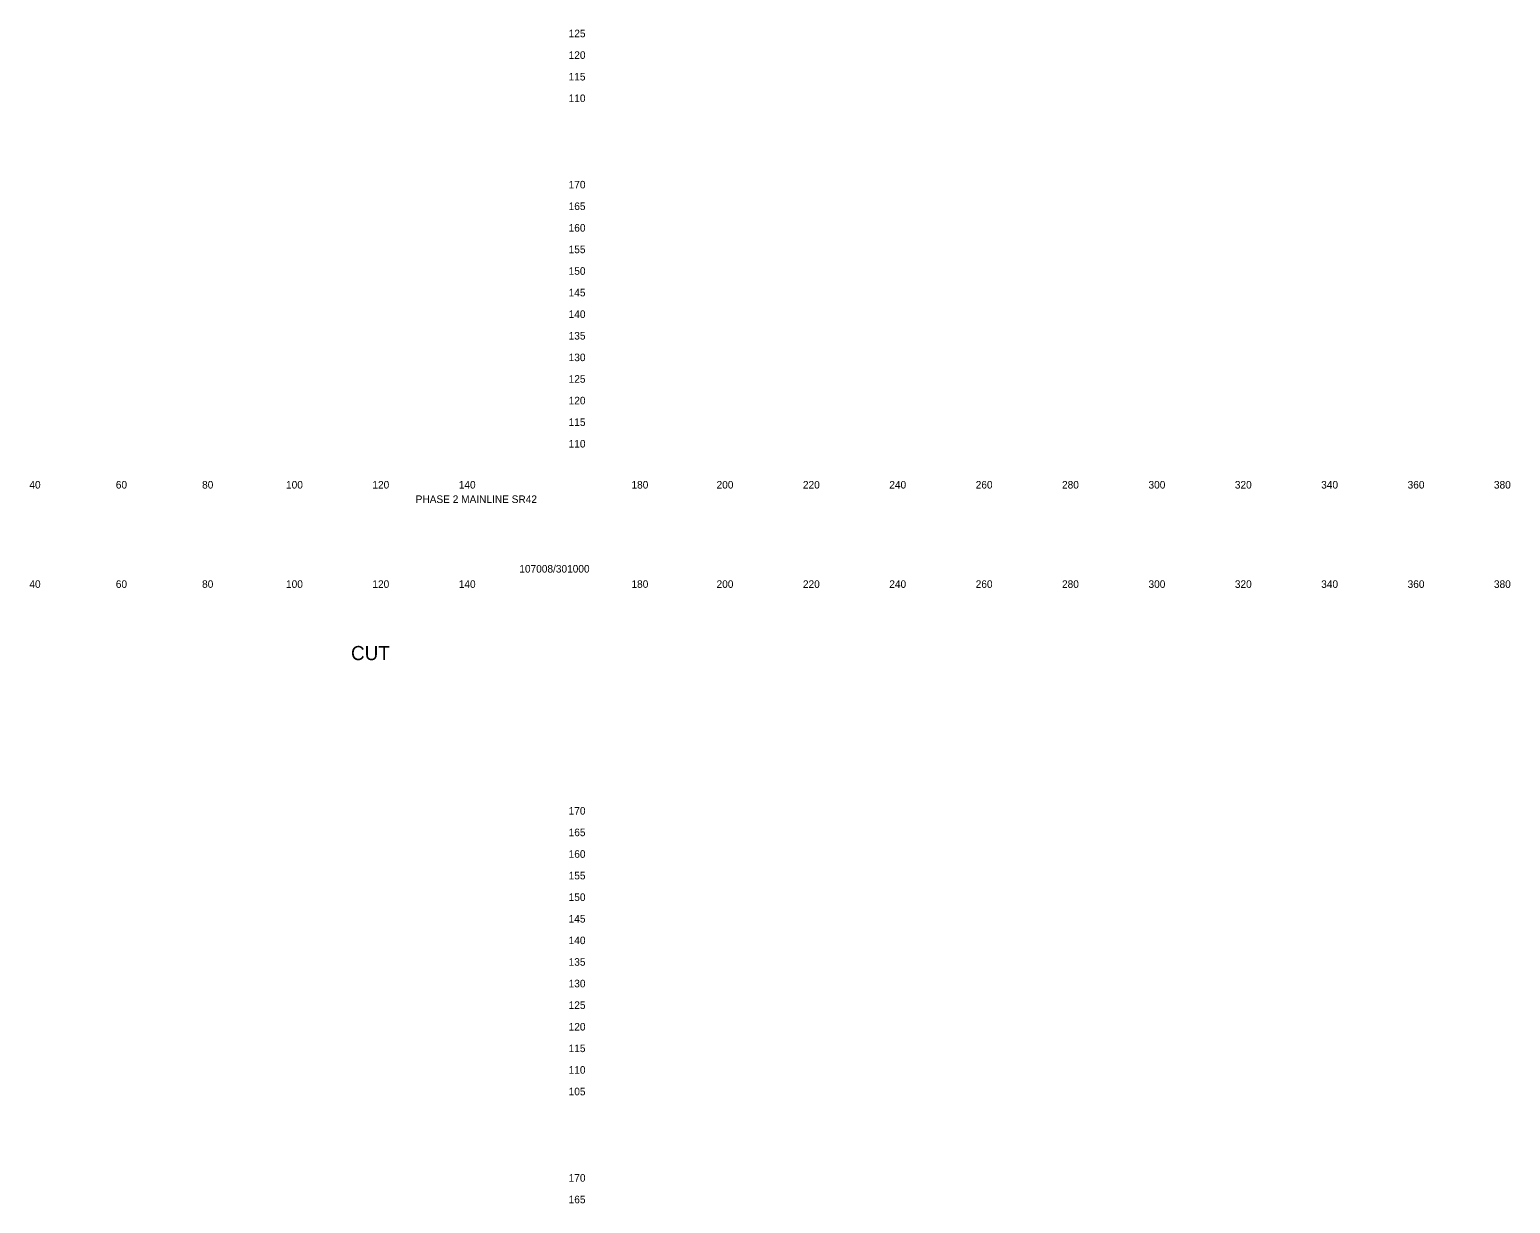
# Model space of a CAD drawing. Extents: x 21281 to 22024, y 6472 to 15208.
# Drawn here: x 21681.3 to 22024.2, y 12749.8 to 13021.6 of the extents above; entities that cross this region are included whole.
import ezdxf

# ---------------------------------------------------------------- set-up
doc = ezdxf.new("R2010")
doc.units = 0
doc.layers.add('XS_SHEET_LABELS_ELEVATION', color=7, linetype='Continuous')
doc.layers.add('XS_SHEET_LABELS_OFFSET', color=7, linetype='Continuous')

msp = doc.modelspace()

# ---------------------------------------------------------------- texts
at = {"layer": 'XS_SHEET_LABELS_ELEVATION'}
for s, p in [('  125  ', (21804.84, 13019.84)), ('  120  ', (21804.84, 13014.84)), ('  115  ', (21804.84, 13009.84)), ('  110  ', (21804.84, 13004.84)), ('  170  ', (21804.84, 12984.84)), ('  165  ', (21804.84, 12979.84)), ('  160  ', (21804.84, 12974.84)), ('  155  ', (21804.84, 12969.84)), ('  150  ', (21804.84, 12964.84)), ('  145  ', (21804.84, 12959.84)), ('  140  ', (21804.84, 12954.84)), ('  135  ', (21804.84, 12949.84)), ('  130  ', (21804.84, 12944.84)), ('  125  ', (21804.84, 12939.84)), ('  120  ', (21804.84, 12934.84)), ('  115  ', (21804.84, 12929.84)), ('  110  ', (21804.84, 12924.84)), ('  170  ', (21804.84, 12839.84)), ('  165  ', (21804.84, 12834.84)), ('  160  ', (21804.84, 12829.84)), ('  155  ', (21804.84, 12824.84)), ('  150  ', (21804.84, 12819.84)), ('  145  ', (21804.84, 12814.84)), ('  140  ', (21804.84, 12809.84)), ('  135  ', (21804.84, 12804.84)), ('  130  ', (21804.84, 12799.84)), ('  125  ', (21804.84, 12794.84)), ('  120  ', (21804.84, 12789.84)), ('  115  ', (21804.84, 12784.84)), ('  110  ', (21804.84, 12779.84)), ('  105  ', (21804.84, 12774.84)), ('  170  ', (21804.84, 12754.84)), ('  165  ', (21804.84, 12749.84))]:
    msp.add_text(s, height=1.75, dxfattribs=at).set_placement(p)
at = {"layer": 'XS_SHEET_LABELS_OFFSET'}
for s, height, p in [('  40  ', 1.75, (21679.95, 12915.34)), ('  60  ', 1.75, (21699.97, 12915.34)), ('  80  ', 1.75, (21719.95, 12915.34)), ('  100  ', 1.75, (21739.39, 12915.34)), ('  120  ', 1.75, (21759.39, 12915.34)), ('  140  ', 1.75, (21779.39, 12915.34)), ('  180  ', 1.75, (21819.39, 12915.34)), ('  200  ', 1.75, (21839.1, 12915.34)), ('  220  ', 1.75, (21859.1, 12915.34)), ('  240  ', 1.75, (21879.1, 12915.34)), ('  260  ', 1.75, (21899.11, 12915.34)), ('  280  ', 1.75, (21919.1, 12915.34)), ('  300  ', 1.75, (21939.13, 12915.34)), ('  320  ', 1.75, (21959.13, 12915.34)), ('  340  ', 1.75, (21979.13, 12915.34)), ('  360  ', 1.75, (21999.14, 12915.34)), ('  380  ', 1.75, (22019.13, 12915.34)), ('PHASE 2 MAINLINE SR42', 1.75, (21770.71, 12912)), ('107008/301000', 1.75, (21794.72, 12895.88)), ('  40  ', 1.75, (21679.95, 12892.34)), ('  60  ', 1.75, (21699.97, 12892.34)), ('  80  ', 1.75, (21719.95, 12892.34)), ('  100  ', 1.75, (21739.39, 12892.34)), ('  120  ', 1.75, (21759.39, 12892.34)), ('  140  ', 1.75, (21779.39, 12892.34)), ('  180  ', 1.75, (21819.39, 12892.34)), ('  200  ', 1.75, (21839.1, 12892.34)), ('  220  ', 1.75, (21859.1, 12892.34)), ('  240  ', 1.75, (21879.1, 12892.34)), ('  260  ', 1.75, (21899.11, 12892.34)), ('  280  ', 1.75, (21919.1, 12892.34)), ('  300  ', 1.75, (21939.13, 12892.34)), ('  320  ', 1.75, (21959.13, 12892.34)), ('  340  ', 1.75, (21979.13, 12892.34)), ('  360  ', 1.75, (21999.14, 12892.34)), ('  380  ', 1.75, (22019.13, 12892.34)), ('CUT', 3.273, (21755.74, 12875.61))]:
    msp.add_text(s, height=height, dxfattribs=at).set_placement(p)

doc.saveas('drawing.dxf')
